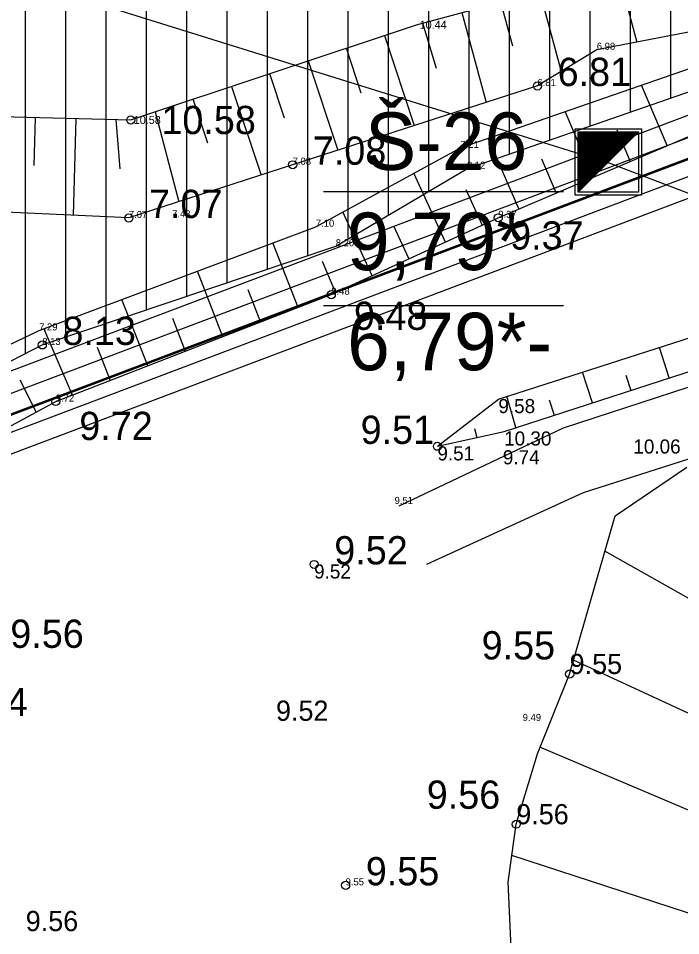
# Model space of a CAD drawing. Extents: x 433497 to 434382, y 6534486 to 6534993.
# Drawn here: x 434060.86 to 434093.7, y 6534741.61 to 6534787.09 of the extents above; entities that cross this region are included whole.
import ezdxf

# ---------------------------------------------------------------- set-up
doc = ezdxf.new("R2010")
doc.units = 0
for name, color, linetype in [('Default', 7, 'Continuous'), ('GEOLPUNKT', 7, 'Continuous'), ('kataster', 7, 'Continuous'), ('KORGUS', 7, 'Continuous'), ('KORGUS-EH2000', 7, 'Continuous'), ('l__x00e4__bil__x00f5__iked', 7, 'Continuous'), ('MAAMUDEL-EH2000', 7, 'Continuous'), ('MOOTKORG-EH2000', 7, 'Continuous'), ('PIIR', 7, 'Continuous'), ('RELJEEF', 7, 'Continuous'), ('TEE', 7, 'Continuous'), ('Täide', 7, 'Continuous'), ('VEEKOGU', 7, 'Continuous')]:
    doc.layers.add(name, color=color, linetype=linetype)

msp = doc.modelspace()

# ---------------------------------------------------------------- linework, layer by layer
at = {"layer": 'Default'}
msp.add_lwpolyline([(433617.12, 6534791.025), (433632.75, 6534606.045), (434137.38, 6534796.515), (434127.69, 6534855.6), (433968.21, 6534911.925), (433942.38, 6534904.035), (433920.99, 6534907.275)], close=True, dxfattribs=at)
msp.add_lwpolyline([(433617.12, 6534791.025), (433632.75, 6534606.045), (434137.38, 6534796.515), (434127.69, 6534855.6), (433968.21, 6534911.925), (433942.38, 6534904.035), (433920.99, 6534907.275)], close=True, dxfattribs=at)
msp.add_lwpolyline([(433617.12, 6534791.025), (433632.75, 6534606.045), (434137.38, 6534796.515), (434127.69, 6534855.6), (433968.21, 6534911.925), (433942.38, 6534904.035), (433920.99, 6534907.275)], close=True, dxfattribs=at)
at = {"layer": 'GEOLPUNKT'}
for p, q in [((434088.615, 6534778.464), (434091.615, 6534781.464)), ((434088.615, 6534778.494), (434091.584, 6534781.464)), ((434088.615, 6534778.565), (434091.514, 6534781.464)), ((434088.615, 6534778.636), (434091.443, 6534781.464)), ((434088.615, 6534778.706), (434091.372, 6534781.464)), ((434088.615, 6534778.777), (434091.302, 6534781.464)), ((434088.615, 6534778.848), (434091.231, 6534781.464)), ((434088.615, 6534778.919), (434091.16, 6534781.464)), ((434088.615, 6534778.989), (434091.089, 6534781.464)), ((434088.615, 6534779.06), (434091.019, 6534781.464)), ((434088.615, 6534779.131), (434090.948, 6534781.464)), ((434088.615, 6534779.201), (434090.877, 6534781.464)), ((434088.615, 6534779.272), (434090.807, 6534781.464)), ((434088.615, 6534779.343), (434090.736, 6534781.464)), ((434088.615, 6534779.414), (434090.665, 6534781.464)), ((434088.615, 6534779.484), (434090.594, 6534781.464)), ((434088.615, 6534779.555), (434090.524, 6534781.464)), ((434088.615, 6534779.626), (434090.453, 6534781.464)), ((434088.615, 6534779.696), (434090.382, 6534781.464)), ((434088.615, 6534779.767), (434090.312, 6534781.464)), ((434088.615, 6534779.838), (434090.241, 6534781.464)), ((434088.615, 6534779.908), (434090.17, 6534781.464)), ((434088.615, 6534779.979), (434090.1, 6534781.464)), ((434088.615, 6534780.05), (434090.029, 6534781.464)), ((434088.615, 6534780.121), (434089.958, 6534781.464)), ((434088.615, 6534780.191), (434089.887, 6534781.464)), ((434088.615, 6534780.262), (434089.817, 6534781.464)), ((434088.615, 6534780.333), (434089.746, 6534781.464)), ((434088.615, 6534780.403), (434089.675, 6534781.464)), ((434088.615, 6534780.474), (434089.605, 6534781.464)), ((434088.615, 6534780.545), (434089.534, 6534781.464)), ((434088.615, 6534780.616), (434089.463, 6534781.464)), ((434088.615, 6534780.686), (434089.392, 6534781.464)), ((434088.615, 6534780.757), (434089.322, 6534781.464)), ((434088.615, 6534780.828), (434089.251, 6534781.464)), ((434088.615, 6534780.898), (434089.18, 6534781.464)), ((434088.615, 6534780.969), (434089.11, 6534781.464)), ((434088.615, 6534781.04), (434089.039, 6534781.464)), ((434088.615, 6534781.111), (434088.968, 6534781.464)), ((434088.615, 6534781.181), (434088.897, 6534781.464)), ((434088.615, 6534781.252), (434088.827, 6534781.464)), ((434088.615, 6534781.323), (434088.756, 6534781.464)), ((434088.615, 6534781.393), (434088.685, 6534781.464)), ((434090.115, 6534779.964), (434090.115, 6534779.964))]:
    msp.add_line(p, q, dxfattribs=at)
for points in [[(434088.474, 6534781.605), (434091.756, 6534781.605), (434091.756, 6534778.323), (434088.474, 6534778.323)], [(434088.615, 6534781.464), (434091.615, 6534781.464), (434091.615, 6534778.464), (434088.615, 6534778.464)]]:
    msp.add_lwpolyline(points, close=True, dxfattribs=at)
for points in [[(434075.985, 6534778.51), (434087.901, 6534778.51)], [(434075.985, 6534772.856), (434087.901, 6534772.856)]]:
    msp.add_lwpolyline(points, dxfattribs=at)
at = {"layer": 'kataster'}
msp.add_lwpolyline([(433617.102, 6534791.002), (433632.769, 6534606.029), (434137.446, 6534796.469), (434127.827, 6534855.589), (433950.026, 6534918.39)], close=True, dxfattribs=at)
at = {"layer": 'KORGUS'}
msp.add_circle((434066.43, 6534782.05), 0.2, dxfattribs=at)
at = {"layer": 'KORGUS-EH2000'}
for centre in [(434086.602, 6534783.735), (434074.461, 6534779.832), (434066.338, 6534777.192), (434084.66, 6534777.201), (434076.377, 6534773.391), (434062.043, 6534770.897), (434062.713, 6534768.089), (434081.64, 6534765.873), (434075.525, 6534760.018), (434088.199, 6534754.582), (434085.551, 6534747.134), (434077.088, 6534744.107)]:
    msp.add_circle(centre, 0.2, dxfattribs=at)
at = {"layer": 'l__x00e4__bil__x00f5__iked'}
msp.add_lwpolyline([(433837.129, 6534901.88), (433863.279, 6534885.992), (433986.579, 6534812.177), (434090.185, 6534779.904), (434120.969, 6534768.153)], dxfattribs=at)
at = {"layer": 'PIIR'}
for points in [[(433632.021, 6534604.835), (434138.248, 6534795.936), (434128.468, 6534856.135), (433968.226, 6534912.818), (433942.33, 6534904.85), (433920.952, 6534908.165), (433616.327, 6534791.524), (433632.021, 6534604.835)], [(433632.732, 6534605.959), (434137.353, 6534796.454), (434127.754, 6534855.539), (433968.208, 6534911.976), (433942.39, 6534904.031), (433921.04, 6534907.341), (433617.174, 6534790.992), (433632.732, 6534605.959)], [(433633.446, 6534604.304), (434134.891, 6534793.6)]]:
    msp.add_lwpolyline(points, dxfattribs=at)
for points in [[(433618.234, 6534790.327), (433921.149, 6534906.313), (433942.464, 6534903.008), (433968.187, 6534910.923), (434126.862, 6534854.794), (434136.235, 6534797.101), (433633.617, 6534607.362)], [(433619.24, 6534789.695), (433634.52, 6534608.851), (434135.141, 6534797.808), (434125.908, 6534854.108), (433968.165, 6534909.82), (433942.53, 6534901.99), (433921.212, 6534905.219)], [(433619.24, 6534789.695), (433634.52, 6534608.851), (434135.141, 6534797.808), (434125.908, 6534854.108), (433968.165, 6534909.82), (433942.53, 6534901.99), (433921.212, 6534905.219)]]:
    msp.add_lwpolyline(points, close=True, dxfattribs=at)
at = {"layer": 'RELJEEF'}
for p, q in [((434090.58, 6534789.458), (434091.536, 6534785.911)), ((434086.717, 6534788.417), (434087.785, 6534784.457)), ((434085.375, 6534785.713), (434084.786, 6534787.896)), ((434082.855, 6534787.376), (434084.057, 6534782.917)), ((434081.592, 6534784.597), (434080.924, 6534786.855)), ((434079.021, 6534786.242), (434080.487, 6534781.769)), ((434077.864, 6534783.387), (434077.124, 6534785.61)), ((434075.226, 6534784.978), (434076.7, 6534780.552)), ((434074.062, 6534782.143), (434073.328, 6534784.346)), ((434093.043, 6534780.78), (434091.764, 6534783.776)), ((434071.431, 6534783.715), (434072.893, 6534779.322)), ((434070.262, 6534780.894), (434069.533, 6534783.083)), ((434067.635, 6534782.451), (434068.812, 6534777.996)), ((434089.364, 6534779.209), (434087.974, 6534782.464)), ((434061.641, 6534779.793), (434061.702, 6534782.172)), ((434063.701, 6534782.12), (434063.578, 6534777.32)), ((434065.907, 6534779.636), (434065.701, 6534782.069)), ((434090.536, 6534781.557), (434091.203, 6534779.994)), ((434085.685, 6534777.639), (434084.163, 6534781.145)), ((434086.802, 6534780.116), (434087.524, 6534778.424)), ((434082.039, 6534775.995), (434080.469, 6534779.408)), ((434083.056, 6534778.606), (434083.856, 6534776.831)), ((434078.405, 6534774.324), (434076.949, 6534777.489)), ((434079.465, 6534776.804), (434080.222, 6534775.159)), ((434074.729, 6534772.751), (434073.471, 6534775.958)), ((434075.917, 6534775.056), (434076.588, 6534773.488)), ((434070.999, 6534771.304), (434069.737, 6534774.559)), ((434072.237, 6534773.644), (434072.864, 6534772.028)), ((434067.27, 6534769.857), (434065.991, 6534773.155)), ((434068.499, 6534772.219), (434069.135, 6534770.581)), ((434063.541, 6534768.41), (434062.127, 6534771.708)), ((434064.762, 6534770.794), (434065.406, 6534769.134)), ((434093.14, 6534769.262), (434092.651, 6534770.774)), ((434089.335, 6534768.03), (434088.841, 6534769.554)), ((434090.992, 6534769.405), (434091.238, 6534768.646)), ((434060.924, 6534769.166), (434061.735, 6534767.56)), ((434085.529, 6534766.798), (434085.082, 6534768.351)), ((434087.184, 6534768.179), (434087.432, 6534767.414)), ((434083.484, 6534766.763), (434083.592, 6534766.308)), ((434081.64, 6534765.873), (434081.64, 6534765.873)), ((434106.893, 6534751.073), (434089.95, 6534760.674)), ((434105.017, 6534747.546), (434088.397, 6534755.272)), ((434103.429, 6534743.874), (434086.728, 6534750.95)), ((434102.041, 6534740.127), (434085.333, 6534745.592))]:
    msp.add_line(p, q, dxfattribs=at)
for points in [[(434002.621, 6534891.199), (434008.357, 6534898.477), (434008.844, 6534898.428), (434009.684, 6534897.899), (434020.673, 6534893.319), (434025.184, 6534891.367), (434026.4, 6534888.82), (434028.53, 6534881.31), (434029.71, 6534869.667), (434036.879, 6534848.772), (434040.385, 6534828.949), (434036.914, 6534815.456), (434039.48, 6534802.82), (434040.271, 6534794.377), (434046.22, 6534786.31), (434052.87, 6534782.4), (434066.43, 6534782.05), (434080.61, 6534786.771), (434096.029, 6534790.927), (434100.314, 6534792.082), (434103.079, 6534792.827), (434103.7, 6534784.75)], [(434042.383, 6534754.563), (434049.423, 6534756.289), (434054.343, 6534758.291), (434054.765, 6534763.79), (434062.713, 6534768.089), (434076.377, 6534773.391), (434084.66, 6534777.201), (434100.89, 6534784.13), (434107.434, 6534785.375)], [(434081.64, 6534765.873), (434081.64, 6534765.873), (434084.665, 6534768.217), (434095.679, 6534771.744), (434103.625, 6534776.038), (434108.041, 6534777.09), (434109.094, 6534777.673), (434109.26, 6534778.654), (434107.434, 6534785.375)], [(434081.64, 6534765.873), (434084.95, 6534766.611), (434096.278, 6534770.278), (434108.089, 6534773.937), (434113.333, 6534774.346), (434114.03, 6534774.964), (434115.274, 6534778.854), (434116.003, 6534779.573)], [(434078.765, 6534722.143), (434083.764, 6534734.729), (434085.385, 6534739.19), (434085.147, 6534744.27), (434085.551, 6534747.134), (434086.598, 6534750.63), (434088.199, 6534754.582), (434090.453, 6534762.425), (434094.014, 6534764.842)]]:
    msp.add_lwpolyline(points, dxfattribs=at)
at = {"layer": 'TEE'}
for points in [[(434079.751, 6534762.916), (434087.895, 6534766.788), (434097.926, 6534770.058), (434097.976, 6534770.078), (434098.026, 6534770.088), (434098.086, 6534770.108), (434109.24, 6534772.987), (434122.531, 6534774.391), (434133.956, 6534776.648), (434144.207, 6534780.731), (434144.327, 6534780.781)], [(434145.12, 6534777.059), (434135.48, 6534773.589), (434121.427, 6534771.071), (434109.25, 6534769.165), (434099.32, 6534766.909), (434088.868, 6534763.558), (434081.095, 6534760.008)]]:
    msp.add_lwpolyline(points, dxfattribs=at)
at = {"layer": 'Täide'}
for p, q in [((434061.213, 6534770.471), (434061.213, 6534875.946)), ((434063.213, 6534771.29), (434063.213, 6534875.289)), ((434065.213, 6534771.962), (434065.213, 6534874.534)), ((434067.213, 6534772.635), (434067.213, 6534873.778)), ((434069.213, 6534773.307), (434069.213, 6534873.023)), ((434071.213, 6534773.979), (434071.213, 6534872.268)), ((434073.213, 6534774.651), (434073.213, 6534871.512)), ((434075.213, 6534775.323), (434075.213, 6534870.757)), ((434077.213, 6534776.152), (434077.213, 6534870.002)), ((434079.213, 6534777.334), (434079.213, 6534869.246)), ((434081.213, 6534778.516), (434081.213, 6534868.491)), ((434083.213, 6534779.673), (434083.213, 6534867.736)), ((434085.213, 6534780.367), (434085.213, 6534866.98)), ((434087.213, 6534781.061), (434087.213, 6534866.225)), ((434089.213, 6534781.755), (434089.213, 6534865.469)), ((434091.213, 6534782.449), (434091.213, 6534864.714)), ((434093.213, 6534783.144), (434093.213, 6534863.959))]:
    msp.add_line(p, q, dxfattribs=at)
msp.add_lwpolyline([(434053.953, 6534766.741), (434062.043, 6534770.897), (434076.601, 6534775.79), (434083.107, 6534779.636), (434100.67, 6534785.732), (434110.817, 6534789.511), (434130.115, 6534796.22), (434132.899, 6534799.258), (434133.017, 6534809.88), (434125.182, 6534852.548), (434123.278, 6534854.722), (434098.113, 6534862.108), (434062.901, 6534875.407), (434022.093, 6534888.443), (434021.059, 6534887.256), (434037.893, 6534864.165), (434021.392, 6534791.18), (434023.3, 6534781.148), (434025.663, 6534773.898), (434039.607, 6534770.357), (434045.083, 6534767.989), (434045.714, 6534765.502), (434044.882, 6534761.539)], dxfattribs=at)
at = {"layer": 'VEEKOGU'}
for points in [[(434100.405, 6534787.207), (434098.317, 6534787.207), (434089.545, 6534785.531), (434086.602, 6534783.735), (434074.461, 6534779.832), (434066.338, 6534777.192), (434050.88, 6534777.91), (434044.67, 6534782.72), (434037.09, 6534794.99), (434032.35, 6534809.44), (434034.87, 6534823.21), (434035.905, 6534837.207), (434031.53, 6534853.98), (434027.762, 6534864.072)], [(434050.128, 6534758.038), (434051.667, 6534760.055), (434049.568, 6534761.922), (434050.115, 6534764.979), (434053.54, 6534767.639), (434061.885, 6534771.617), (434075.613, 6534776.761), (434082.778, 6534780.666), (434100.118, 6534786.667), (434100.405, 6534787.207)]]:
    msp.add_lwpolyline(points, dxfattribs=at)

# ---------------------------------------------------------------- texts
at = {"layer": 'GEOLPUNKT'}
for s, p in [('Š-26', (434078.047, 6534779.573)), ('9,79*', (434077.153, 6534774.607)), ('6,79*-', (434077.163, 6534769.642))]:
    msp.add_text(s, height=2.85, dxfattribs=at).set_placement(p)
at = {"layer": 'KORGUS-EH2000'}
for s, p in [('6.81', (434087.602, 6534783.735)), (' 10.58', (434067.43, 6534781.35)), ('7.08', (434075.461, 6534779.832)), ('7.07', (434067.338, 6534777.192)), ('9.37', (434085.246, 6534775.626)), ('9.48', (434077.501, 6534771.644)), ('8.13', (434063.043, 6534770.897)), ('9.72', (434063.879, 6534766.184)), ('9.51', (434077.832, 6534765.992)), ('9.52', (434076.525, 6534760.018)), ('9.56', (434060.457, 6534755.88)), ('9.55', (434083.835, 6534755.307)), ('9.54', (434057.682, 6534752.495)), ('9.56', (434081.111, 6534747.902)), ('9.55', (434078.088, 6534744.107))]:
    msp.add_text(s, height=1.4, dxfattribs=at).set_placement(p)
at = {"layer": 'MAAMUDEL-EH2000'}
for s, p in [(' 10.44', (434080.61, 6534786.571)), (' 10.58', (434066.43, 6534781.85))]:
    msp.add_text(s, height=0.4, dxfattribs=at).set_placement(p)
at = {"layer": 'MOOTKORG-EH2000'}
for s, height, p in [('6.98', 0.35, (434089.545, 6534785.531)), ('6.81', 0.35, (434086.602, 6534783.735)), ('7.21', 0.35, (434082.778, 6534780.666)), ('7.08', 0.35, (434074.461, 6534779.832)), ('8.12', 0.35, (434083.107, 6534779.636)), ('7.07', 0.35, (434066.338, 6534777.192)), ('7.48', 0.35, (434068.481, 6534777.22)), ('9.37', 0.35, (434084.66, 6534777.201)), ('7.10', 0.35, (434075.613, 6534776.761)), ('8.20', 0.35, (434076.601, 6534775.79)), ('9.48', 0.35, (434076.377, 6534773.391)), ('7.29', 0.35, (434061.885, 6534771.617)), ('8.13', 0.35, (434062.043, 6534770.897)), ('9.72', 0.35, (434062.713, 6534768.089)), ('9.58', 0.7, (434084.665, 6534767.517)), ('10.30', 0.7, (434084.95, 6534765.911)), ('10.06', 0.7, (434091.36, 6534765.514)), ('9.51', 0.7, (434081.64, 6534765.173)), ('9.74', 0.7, (434084.887, 6534764.978)), ('9.51', 0.35, (434079.517, 6534763.014)), ('9.52', 0.7, (434075.525, 6534759.318)), ('9.55', 1, (434088.199, 6534754.582)), ('9.52', 1, (434073.634, 6534752.264)), ('9.49', 0.35, (434085.87, 6534752.256)), ('9.56', 1, (434085.551, 6534747.134)), ('9.55', 0.35, (434077.088, 6534744.107)), ('9.56', 1, (434061.222, 6534741.838))]:
    msp.add_text(s, height=height, dxfattribs=at).set_placement(p)

doc.saveas('drawing.dxf')
